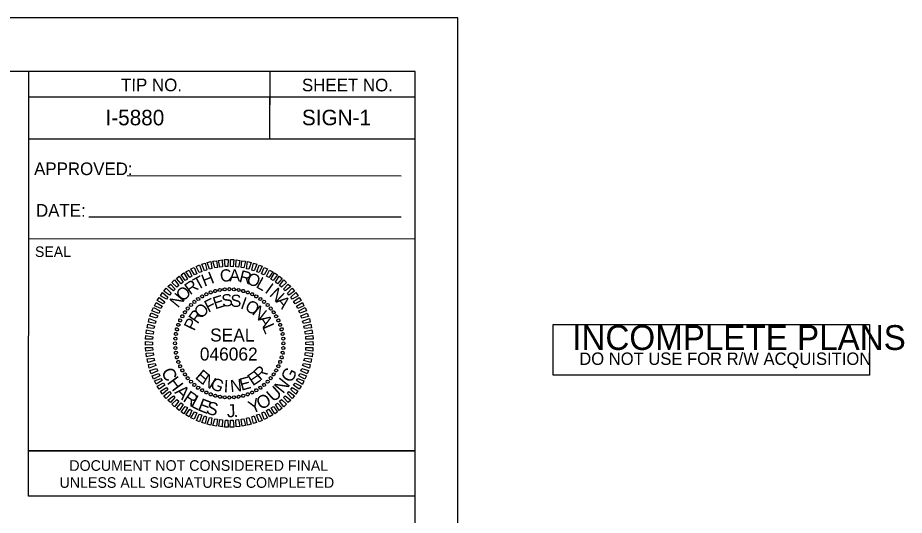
# Model space of a CAD drawing. Extents: x 49201 to 52602, y 49383 to 50479.
# Drawn here: x 52173 to 52602.1, y 50238.5 to 50479.3 of the extents above; entities that cross this region are included whole.
import ezdxf

# ---------------------------------------------------------------- set-up
doc = ezdxf.new("R2010")
doc.units = 0
for name, color, linetype in [('Default', 7, 'Continuous'), ('Old_Level_10', 7, 'Continuous'), ('Old_Level_18', 7, 'Continuous'), ('Old_Level_2', 7, 'Continuous'), ('Old_Level_4', 7, 'Continuous'), ('Old_Level_50', 7, 'Continuous'), ('Sheet Plot Border Outside CELL', 7, 'Continuous'), ('Sheet Sticker Exception Certification CELL', 7, 'Continuous'), ('Sheet Sticker Incomplete CELL', 7, 'Continuous'), ('Sheet Title CELL', 7, 'Continuous')]:
    doc.layers.add(name, color=color, linetype=linetype)

msp = doc.modelspace()

# ---------------------------------------------------------------- linework, layer by layer
at = {"layer": 'Old_Level_10'}
for p, q in [((52295.09, 50420.67), (52295.11, 50453.21)), ((52295.09, 50428.25), (52295.11, 50453.21)), ((52365.34, 50453.17), (52365.34, 50453.17)), ((52178.35, 50441.05), (52295.1, 50440.98)), ((52295.1, 50440.98), (52365.34, 50440.95)), ((52178.34, 50420.73), (52365.33, 50420.63)), ((52226.02, 50402.83), (52358.63, 50402.77)), ((52207.33, 50382.93), (52358.62, 50382.86))]:
    msp.add_line(p, q, dxfattribs=at)
at = {"layer": 'Old_Level_18'}
msp.add_lwpolyline([(52365.34, 50453.17), (50865.34, 50453.17), (50865.34, 49403.17), (52365.34, 49403.17)], close=True, dxfattribs=at)
at = {"layer": 'Old_Level_2'}
for p, q in [((52273.08, 50347.83), (52273.08, 50347.83)), ((52275.38, 50347.93), (52275.38, 50347.93)), ((52277.69, 50347.81), (52277.69, 50347.81)), ((52262.27, 50344.4), (52262.27, 50344.4)), ((52264.29, 50345.48), (52264.29, 50345.48)), ((52266.36, 50346.36), (52266.36, 50346.36)), ((52268.55, 50347.02), (52268.55, 50347.02)), ((52270.84, 50347.48), (52270.84, 50347.48)), ((52279.94, 50347.48), (52279.94, 50347.48)), ((52282.14, 50347.05), (52282.14, 50347.05)), ((52284.35, 50346.36), (52284.35, 50346.36)), ((52286.46, 50345.45), (52286.46, 50345.45)), ((52288.52, 50344.44), (52288.52, 50344.44)), ((52256.8, 50340.23), (52256.8, 50340.23)), ((52258.49, 50341.83), (52258.49, 50341.83)), ((52260.3, 50343.17), (52260.3, 50343.17)), ((52290.42, 50343.17), (52290.42, 50343.17)), ((52292.28, 50341.79), (52292.28, 50341.79)), ((52293.93, 50340.25), (52293.93, 50340.25)), ((52252.6, 50334.82), (52252.6, 50334.82)), ((52253.88, 50336.73), (52253.88, 50336.73)), ((52255.26, 50338.58), (52255.26, 50338.58)), ((52295.52, 50338.55), (52295.52, 50338.55)), ((52296.86, 50336.74), (52296.86, 50336.74)), ((52298.1, 50334.78), (52298.1, 50334.78)), ((52250.69, 50330.66), (52250.69, 50330.66)), ((52251.59, 50332.76), (52251.59, 50332.76)), ((52299.18, 50332.76), (52299.18, 50332.76)), ((52300.05, 50330.68), (52300.05, 50330.68)), ((52249.56, 50326.24), (52249.56, 50326.24)), ((52249.99, 50328.45), (52249.99, 50328.45)), ((52300.72, 50328.5), (52300.72, 50328.5)), ((52301.18, 50326.2), (52301.18, 50326.2)), ((52249.23, 50323.99), (52249.23, 50323.99)), ((52301.53, 50323.96), (52301.53, 50323.96)), ((52249.12, 50321.69), (52249.12, 50321.69)), ((52249.21, 50319.39), (52249.21, 50319.39)), ((52275.37, 50321.67), (52275.37, 50321.67)), ((52301.51, 50319.36), (52301.51, 50319.36)), ((52301.62, 50321.66), (52301.62, 50321.66)), ((52249.56, 50317.14), (52249.56, 50317.14)), ((52250.02, 50314.85), (52250.02, 50314.85)), ((52300.75, 50314.9), (52300.75, 50314.9)), ((52301.18, 50317.1), (52301.18, 50317.1)), ((52250.69, 50312.67), (52250.69, 50312.67)), ((52251.56, 50310.59), (52251.56, 50310.59)), ((52299.15, 50310.58), (52299.15, 50310.58)), ((52300.05, 50312.69), (52300.05, 50312.69)), ((52252.64, 50308.57), (52252.64, 50308.57)), ((52253.88, 50306.6), (52253.88, 50306.6)), ((52255.22, 50304.8), (52255.22, 50304.8)), ((52295.49, 50304.77), (52295.49, 50304.77)), ((52296.87, 50306.62), (52296.87, 50306.62)), ((52298.14, 50308.53), (52298.14, 50308.53)), ((52256.82, 50303.1), (52256.82, 50303.1)), ((52258.46, 50301.56), (52258.46, 50301.56)), ((52292.25, 50301.52), (52292.25, 50301.52)), ((52293.95, 50303.12), (52293.95, 50303.12)), ((52260.32, 50300.18), (52260.32, 50300.18)), ((52262.22, 50298.9), (52262.22, 50298.9)), ((52264.28, 50297.89), (52264.28, 50297.89)), ((52266.39, 50296.99), (52266.39, 50296.99)), ((52268.6, 50296.3), (52268.6, 50296.3)), ((52282.19, 50296.32), (52282.19, 50296.32)), ((52284.38, 50296.99), (52284.38, 50296.99)), ((52286.45, 50297.86), (52286.45, 50297.86)), ((52288.48, 50298.94), (52288.48, 50298.94)), ((52290.44, 50300.18), (52290.44, 50300.18)), ((52270.8, 50295.86), (52270.8, 50295.86)), ((52273.06, 50295.54), (52273.06, 50295.54)), ((52275.36, 50295.42), (52275.36, 50295.42)), ((52277.66, 50295.51), (52277.66, 50295.51)), ((52279.9, 50295.87), (52279.9, 50295.87))]:
    msp.add_line(p, q, dxfattribs=at)
for points in [[(52265.85, 50357.54), (52264.7, 50360.81), (52266.47, 50361.21), (52266.95, 50357.82)], [(52268.35, 50358.16), (52267.46, 50361.49), (52269.18, 50361.68), (52269.61, 50358.34)], [(52270.86, 50358.52), (52270.22, 50361.85), (52272, 50362.09), (52272.11, 50358.69)], [(52273.47, 50358.82), (52273.15, 50362.22), (52274.87, 50362.19), (52274.72, 50358.79)], [(52275.98, 50358.81), (52275.92, 50362.21), (52277.64, 50362.19), (52277.23, 50358.78)], [(52278.59, 50358.7), (52278.74, 50362.11), (52280.48, 50361.82), (52279.85, 50358.52)], [(52281.11, 50358.33), (52281.52, 50361.68), (52283.25, 50361.45), (52282.37, 50358.19)], [(52283.79, 50357.8), (52284.25, 50361.21), (52286.04, 50360.82), (52284.89, 50357.56)], [(52256.3, 50353.5), (52254.32, 50356.29), (52255.92, 50357.16), (52257.28, 50354.15)], [(52258.53, 50354.8), (52256.8, 50357.7), (52258.41, 50358.46), (52259.67, 50355.29)], [(52260.81, 50355.94), (52259.4, 50358.94), (52260.96, 50359.6), (52262.11, 50356.27)], [(52263.36, 50356.82), (52262.1, 50359.93), (52263.71, 50360.43), (52264.45, 50357.2)], [(52286.31, 50357.16), (52287.04, 50360.42), (52288.67, 50359.93), (52287.41, 50356.82)], [(52288.68, 50356.26), (52289.82, 50359.58), (52291.3, 50358.98), (52289.89, 50355.92)], [(52291.05, 50355.31), (52292.3, 50358.42), (52293.93, 50357.72), (52292.21, 50354.76)], [(52293.47, 50354.15), (52294.83, 50357.16), (52296.42, 50356.3), (52294.48, 50353.54)], [(52250, 50348.9), (52247.66, 50351.16), (52248.9, 50352.43), (52250.98, 50349.64)], [(52252.07, 50350.55), (52249.77, 50353.02), (52251.17, 50354.15), (52253.05, 50351.25)], [(52254.02, 50352.16), (52252.04, 50354.79), (52253.39, 50355.81), (52255.16, 50352.8)], [(52295.54, 50352.78), (52297.31, 50355.84), (52298.69, 50354.77), (52296.7, 50352.17)], [(52297.71, 50351.24), (52299.59, 50354.15), (52300.97, 50353.03), (52298.71, 50350.53)], [(52299.72, 50349.66), (52301.82, 50352.41), (52303.1, 50351.18), (52300.73, 50348.89)], [(52246.51, 50345.02), (52243.76, 50347.01), (52244.89, 50348.39), (52247.23, 50345.97)], [(52248.31, 50347.04), (52245.61, 50349.13), (52246.89, 50350.36), (52249.13, 50347.89)], [(52301.64, 50347.86), (52303.84, 50350.36), (52305.12, 50349.13), (52302.44, 50347.04)], [(52303.5, 50346.01), (52305.86, 50348.41), (52306.99, 50347.01), (52304.25, 50344.98)], [(52243.45, 50340.88), (52240.49, 50342.4), (52241.51, 50343.88), (52244.27, 50341.84)], [(52244.98, 50343), (52242.13, 50344.73), (52243.09, 50346.26), (52245.64, 50344.01)], [(52305.1, 50344), (52307.63, 50346.24), (52308.65, 50344.74), (52305.75, 50343.02)], [(52306.5, 50341.88), (52309.24, 50343.92), (52310.26, 50342.36), (52307.25, 50340.85)], [(52242.23, 50338.61), (52239.23, 50339.87), (52239.99, 50341.5), (52242.84, 50339.62)], [(52307.9, 50339.6), (52310.8, 50341.48), (52311.5, 50339.88), (52308.54, 50338.62)], [(52240.22, 50333.87), (52236.97, 50334.76), (52237.62, 50336.39), (52240.78, 50334.98)], [(52241.23, 50336.19), (52237.97, 50337.34), (52238.72, 50338.97), (52241.73, 50337.35)], [(52308.98, 50337.37), (52312.04, 50339), (52312.75, 50337.34), (52309.53, 50336.23)], [(52309.97, 50334.93), (52313.13, 50336.35), (52313.74, 50334.74), (52310.51, 50333.84)], [(52238.85, 50328.83), (52235.6, 50329.19), (52235.93, 50330.97), (52239.25, 50329.93)], [(52239.48, 50331.35), (52236.23, 50331.97), (52236.57, 50333.7), (52239.88, 50332.45)], [(52310.85, 50332.44), (52314.17, 50333.7), (52314.52, 50331.98), (52311.23, 50331.35)], [(52311.52, 50329.94), (52314.8, 50330.99), (52315.14, 50329.22), (52311.85, 50328.85)], [(52238.48, 50326.15), (52235.12, 50326.41), (52235.3, 50328.19), (52238.72, 50327.41)], [(52312.03, 50327.44), (52315.42, 50328.23), (52315.61, 50326.46), (52312.27, 50326.19)], [(52238.25, 50321.03), (52234.86, 50320.81), (52234.83, 50322.59), (52238.23, 50322.28)], [(52238.26, 50323.64), (52234.86, 50323.69), (52234.93, 50325.41), (52238.34, 50324.9)], [(52312.39, 50324.93), (52315.78, 50325.41), (52315.92, 50323.64), (52312.52, 50323.68)], [(52312.49, 50322.32), (52315.89, 50322.54), (52315.92, 50320.76), (52312.51, 50321.07)], [(52238.35, 50318.41), (52234.96, 50317.94), (52234.82, 50319.71), (52238.22, 50319.67)], [(52312.48, 50319.71), (52315.88, 50319.66), (52315.81, 50317.93), (52312.4, 50318.45)], [(52238.71, 50315.91), (52235.32, 50315.12), (52235.13, 50316.89), (52238.48, 50317.16)], [(52239.22, 50313.41), (52235.95, 50312.36), (52235.6, 50314.13), (52238.89, 50314.5)], [(52311.89, 50314.52), (52315.14, 50314.16), (52314.81, 50312.37), (52311.49, 50313.41)], [(52312.27, 50317.19), (52315.62, 50316.94), (52315.44, 50315.16), (52312.03, 50315.93)], [(52239.89, 50310.91), (52236.57, 50309.65), (52236.22, 50311.37), (52239.51, 50312)], [(52240.77, 50308.41), (52237.61, 50307), (52237, 50308.61), (52240.23, 50309.5)], [(52310.52, 50309.47), (52313.78, 50308.59), (52313.12, 50306.96), (52309.96, 50308.37)], [(52311.26, 50312), (52314.51, 50311.37), (52314.18, 50309.64), (52310.86, 50310.89)], [(52241.76, 50305.97), (52238.7, 50304.35), (52237.99, 50306.01), (52241.21, 50307.11)], [(52242.84, 50303.74), (52239.95, 50301.86), (52239.24, 50303.47), (52242.2, 50304.73)], [(52308.51, 50304.73), (52311.51, 50303.48), (52310.76, 50301.84), (52307.9, 50303.73)], [(52309.51, 50307.16), (52312.77, 50306.01), (52312.02, 50304.38), (52309.01, 50306)], [(52244.24, 50301.47), (52241.51, 50299.43), (52240.48, 50300.98), (52243.49, 50302.5)], [(52307.29, 50302.46), (52310.25, 50300.95), (52309.23, 50299.46), (52306.47, 50301.51)], [(52245.64, 50299.35), (52243.11, 50297.11), (52242.09, 50298.61), (52244.99, 50300.33)], [(52247.24, 50297.34), (52244.88, 50294.94), (52243.76, 50296.33), (52246.49, 50298.37)], [(52249.1, 50295.49), (52246.9, 50292.99), (52245.62, 50294.22), (52248.31, 50296.31)], [(52302.43, 50296.31), (52305.14, 50294.21), (52303.85, 50292.99), (52301.61, 50295.46)], [(52304.23, 50298.33), (52306.98, 50296.34), (52305.86, 50294.96), (52303.51, 50297.38)], [(52305.76, 50300.34), (52308.62, 50298.62), (52307.65, 50297.08), (52305.1, 50299.34)], [(52251.02, 50293.69), (52248.92, 50290.93), (52247.65, 50292.17), (52250.01, 50294.46)], [(52253.03, 50292.1), (52251.15, 50289.19), (52249.77, 50290.32), (52252.03, 50292.82)], [(52298.68, 50292.79), (52300.97, 50290.32), (52299.58, 50289.2), (52297.69, 50292.1)], [(52300.74, 50294.45), (52303.08, 50292.19), (52301.85, 50290.92), (52299.76, 50293.7)], [(52255.2, 50290.57), (52253.43, 50287.51), (52252.05, 50288.58), (52254.04, 50291.18)], [(52257.27, 50289.2), (52255.91, 50286.19), (52254.32, 50287.05), (52256.26, 50289.81)], [(52259.69, 50288.04), (52258.44, 50284.93), (52256.81, 50285.63), (52258.53, 50288.59)], [(52292.21, 50288.55), (52293.94, 50285.65), (52292.33, 50284.89), (52291.07, 50288.06)], [(52294.44, 50289.84), (52296.42, 50287.05), (52294.82, 50286.19), (52293.46, 50289.2)], [(52296.72, 50291.19), (52298.7, 50288.56), (52297.36, 50287.54), (52295.58, 50290.54)], [(52262.06, 50287.08), (52260.92, 50283.77), (52259.44, 50284.37), (52260.86, 50287.43)], [(52264.43, 50286.18), (52263.71, 50282.93), (52262.08, 50283.42), (52263.33, 50286.53)], [(52266.95, 50285.55), (52266.49, 50282.14), (52264.71, 50282.53), (52265.85, 50285.79)], [(52269.63, 50285.02), (52269.22, 50281.66), (52267.49, 50281.9), (52268.37, 50285.15)], [(52272.15, 50284.64), (52272, 50281.24), (52270.27, 50281.53), (52270.89, 50284.83)], [(52274.76, 50284.53), (52274.82, 50281.13), (52273.1, 50281.16), (52273.51, 50284.56)], [(52277.27, 50284.52), (52277.6, 50281.13), (52275.87, 50281.15), (52276.02, 50284.55)], [(52279.88, 50284.83), (52280.52, 50281.5), (52278.74, 50281.26), (52278.63, 50284.65)], [(52282.39, 50285.19), (52283.28, 50281.86), (52281.56, 50281.67), (52281.14, 50285.01)], [(52284.89, 50285.81), (52286.04, 50282.53), (52284.27, 50282.14), (52283.79, 50285.53)], [(52287.38, 50286.53), (52288.64, 50283.42), (52287.03, 50282.92), (52286.29, 50286.15)], [(52289.93, 50287.41), (52291.34, 50284.4), (52289.79, 50283.75), (52288.63, 50287.08)]]:
    msp.add_lwpolyline(points, close=True, dxfattribs=at)
for centre, major_axis in [((52268.58, 50347.01), (-0.195, 0.727)), ((52270.82, 50347.5), (-0.131, 0.742)), ((52273.09, 50347.8), (-0.066, 0.75)), ((52275.37, 50347.9), (0, 0.753)), ((52277.66, 50347.8), (0.066, 0.75)), ((52279.93, 50347.5), (0.131, 0.742)), ((52282.16, 50347.01), (0.195, 0.727)), ((52260.33, 50343.16), (-0.432, 0.617)), ((52262.26, 50344.39), (-0.376, 0.652)), ((52264.29, 50345.44), (-0.318, 0.682)), ((52266.4, 50346.32), (-0.258, 0.708)), ((52284.34, 50346.32), (0.258, 0.708)), ((52286.46, 50345.44), (0.318, 0.682)), ((52288.48, 50344.39), (0.376, 0.652)), ((52290.41, 50343.16), (0.432, 0.617)), ((52255.28, 50338.53), (-0.577, 0.484)), ((52256.83, 50340.22), (-0.532, 0.532)), ((52258.51, 50341.77), (-0.484, 0.577)), ((52292.23, 50341.77), (0.484, 0.577)), ((52293.92, 50340.22), (0.532, 0.532)), ((52295.46, 50338.53), (0.577, 0.484)), ((52252.66, 50334.79), (-0.652, 0.376)), ((52253.89, 50336.72), (-0.617, 0.432)), ((52296.86, 50336.72), (0.617, 0.432)), ((52298.08, 50334.79), (0.652, 0.376)), ((52250.72, 50330.64), (-0.708, 0.258)), ((52251.6, 50332.76), (-0.682, 0.318)), ((52299.14, 50332.76), (0.682, 0.318)), ((52300.02, 50330.64), (0.708, 0.258)), ((52249.54, 50326.23), (-0.742, 0.131)), ((52250.04, 50328.46), (-0.727, 0.195)), ((52300.71, 50328.46), (0.727, 0.195)), ((52301.2, 50326.23), (0.742, 0.131)), ((52249.14, 50321.67), (-0.753, 0)), ((52249.24, 50323.96), (-0.75, 0.066)), ((52301.5, 50323.96), (0.75, 0.066)), ((52301.6, 50321.67), (0.753, 0)), ((52249.24, 50319.39), (-0.75, -0.066)), ((52249.54, 50317.12), (-0.742, -0.131)), ((52301.2, 50317.12), (0.742, -0.131)), ((52301.5, 50319.39), (0.75, -0.066)), ((52250.04, 50314.89), (-0.727, -0.195)), ((52250.72, 50312.7), (-0.708, -0.258)), ((52300.02, 50312.7), (0.708, -0.258)), ((52300.71, 50314.89), (0.727, -0.195)), ((52251.6, 50310.59), (-0.682, -0.318)), ((52252.66, 50308.56), (-0.652, -0.376)), ((52298.08, 50308.56), (0.652, -0.376)), ((52299.14, 50310.59), (0.682, -0.318)), ((52253.89, 50306.63), (-0.617, -0.432)), ((52255.28, 50304.81), (-0.577, -0.484)), ((52295.46, 50304.81), (0.577, -0.484)), ((52296.86, 50306.63), (0.617, -0.432)), ((52256.83, 50303.13), (-0.532, -0.532)), ((52258.51, 50301.58), (-0.484, -0.577)), ((52260.33, 50300.19), (-0.432, -0.617)), ((52290.41, 50300.19), (0.432, -0.617)), ((52292.23, 50301.58), (0.484, -0.577)), ((52293.92, 50303.13), (0.532, -0.532)), ((52262.26, 50298.96), (-0.376, -0.652)), ((52264.29, 50297.9), (-0.318, -0.682)), ((52266.4, 50297.03), (-0.258, -0.708)), ((52268.58, 50296.34), (-0.195, -0.727)), ((52270.82, 50295.84), (-0.131, -0.742)), ((52273.09, 50295.55), (-0.066, -0.75)), ((52275.37, 50295.45), (0, -0.753)), ((52277.66, 50295.55), (0.066, -0.75)), ((52279.93, 50295.84), (0.131, -0.742)), ((52282.16, 50296.34), (0.195, -0.727)), ((52284.34, 50297.03), (0.258, -0.708)), ((52286.46, 50297.9), (0.318, -0.682)), ((52288.48, 50298.96), (0.376, -0.652))]:
    msp.add_ellipse(centre, major_axis=major_axis, ratio=0.999708, dxfattribs=at)
at = {"layer": 'Old_Level_50'}
msp.add_line((52386.04, 50479.27), (52386.04, 50479.27), dxfattribs=at)
at = {"layer": 'Sheet Plot Border Outside CELL'}
msp.add_lwpolyline([(52386.04, 50479.27), (50703.13, 50479.27), (50703.13, 49383.36), (52386.04, 49383.36)], close=True, dxfattribs=at)
at = {"layer": 'Sheet Sticker Exception Certification CELL'}
for p, q in [((52178.27, 50247.68), (52178.27, 50269.65)), ((52178.27, 50269.65), (52365.26, 50269.65)), ((52365.26, 50269.63), (52365.26, 50247.67)), ((52365.26, 50247.68), (52178.27, 50247.68))]:
    msp.add_line(p, q, dxfattribs=at)
at = {"layer": 'Sheet Sticker Incomplete CELL'}
msp.add_lwpolyline([(52432.08, 50306.29), (52432.08, 50330.78), (52585.24, 50330.78), (52585.24, 50306.29)], close=True, dxfattribs=at)
at = {"layer": 'Sheet Title CELL'}
for p, q in [((52178.34, 50428.31), (52178.35, 50453.26)), ((52178.32, 50381.13), (52178.34, 50428.31)), ((52178.27, 50269.73), (52178.32, 50381.13)), ((52178.32, 50372.39), (52365.3, 50372.3)), ((52365.26, 50269.65), (52178.27, 50269.73))]:
    msp.add_line(p, q, dxfattribs=at)

# ---------------------------------------------------------------- texts
at = {"layer": 'Default'}
for s, rotation, p in [('C', 297.1998, (52242.25, 50307.94)), ('G', 61.7997, (52305.48, 50302.18)), ('H', 306.6436, (52244.95, 50302.69)), ('N', 51.2288, (52301.4, 50296.98)), ('A', 316.4834, (52248.64, 50297.77)), ('U', 41.4347, (52296.82, 50292.92)), ('R', 325.196, (52252.57, 50294)), ('L', 332.5683, (52256.3, 50291.3)), ('O', 30.0413, (52290.72, 50289.25)), ('E', 338.7524, (52259.69, 50289.42)), ('S', 345.7591, (52263.74, 50287.75)), ('J', 3.0321, (52274.33, 50285.82)), ('Y', 22.2425, (52286.18, 50287.47)), ('.', 8.2139, (52277.57, 50285.87))]:
    msp.add_text(s, height=6.27, rotation=rotation, dxfattribs=at).set_placement(p)
at = {"layer": 'Old_Level_10'}
for s, height, p in [('TIP NO.', 6.11, (52223, 50443.7)), ('SHEET NO.', 6.11, (52310.55, 50443.65)), ('SEAL', 5.094, (52181.34, 50363.48))]:
    msp.add_text(s, height=height, rotation=359.9683, dxfattribs=at).set_placement(p)
at = {"layer": 'Old_Level_2'}
for s, height, rotation, p in [('H', 5.9, 21.6194, (52263.34, 50349.02)), ('C', 5.9, 7.2198, (52271.25, 50351.25)), ('A', 5.9, 0.0203, (52275.37, 50351.64)), ('R', 5.9, 345.6211, (52279.77, 50351.51)), ('R', 5.9, 36.0205, (52256.45, 50344.88)), ('T', 5.9, 28.8197, (52259.97, 50347.24)), ('O', 5.9, 338.4211, (52283.28, 50350.78)), ('L', 5.9, 331.2208, (52287.92, 50348.93)), ('O', 5.9, 43.2217, (52252.9, 50341.57)), ('I', 5.9, 324.0201, (52292.2, 50346.49)), ('N', 5.9, 316.8189, (52294.47, 50344.91)), ('N', 5.9, 50.4235, (52250.55, 50338.5)), ('F', 5.9, 26.967, (52265.23, 50336.45)), ('E', 5.9, 17.611, (52268.55, 50338.08)), ('S', 5.9, 8.2556, (52272.14, 50339.24)), ('S', 5.9, 358.9004, (52275.9, 50339.36)), ('I', 5.9, 340.1896, (52280.41, 50338.71)), ('A', 5.9, 309.6171, (52297.61, 50341.88)), ('O', 5.9, 45.6812, (52261.83, 50333.31)), ('O', 5.9, 330.8335, (52282.51, 50338.01)), ('N', 5.9, 321.4766, (52286.05, 50335.98)), ('R', 5.9, 55.0396, (52260.05, 50330.72)), ('P', 5.9, 64.3989, (52258.43, 50327.34)), ('A', 5.9, 302.7602, (52289.08, 50333.31)), ('L', 5.9, 293.4008, (52291.18, 50329.74)), ('SEAL', 6.273, 360, (52266.1, 50322.56)), ('046062', 6.275, 360, (52261.13, 50313.35)), ('E', 5.9, 319.2769, (52258.51, 50305.01)), ('R', 5.9, 43.4814, (52290.44, 50303.37)), ('N', 5.9, 328.6339, (52261.69, 50302.24)), ('G', 5.9, 337.9902, (52265.71, 50299.96)), ('E', 5.9, 15.4117, (52281.26, 50298.71)), ('E', 5.9, 34.1241, (52286.77, 50300.85)), ('I', 5.9, 356.7012, (52272.59, 50298.09)), ('N', 5.9, 6.0564, (52276.1, 50298))]:
    msp.add_text(s, height=height, rotation=rotation, dxfattribs=at).set_placement(p)
at = {"layer": 'Old_Level_4'}
for s, p in [('APPROVED:', (52180.92, 50403.12)), ('DATE:', (52181.83, 50382.98))]:
    msp.add_text(s, height=6.11, rotation=359.9683, dxfattribs=at).set_placement(p)
at = {"layer": 'Sheet Sticker Exception Certification CELL'}
for s, p in [('DOCUMENT NOT CONSIDERED FINAL', (52197.96, 50259.98)), ('UNLESS ALL SIGNATURES COMPLETED', (52193.22, 50251.75))]:
    msp.add_text(s, height=5.1412, dxfattribs=at).set_placement(p)
at = {"layer": 'Sheet Sticker Incomplete CELL'}
for s, height, p in [('INCOMPLETE PLANS', 12.0025, (52441.4, 50318.48)), ('DO NOT USE FOR R/W ACQUISITION', 6.0012, (52444.79, 50311.24))]:
    msp.add_text(s, height=height, dxfattribs=at).set_placement(p)
at = {"layer": 'Sheet Title CELL'}
for s, p in [('I-5880', (52215.48, 50427.21)), ('SIGN-1', (52310.54, 50427.24))]:
    msp.add_text(s, height=7.5, rotation=359.9683, dxfattribs=at).set_placement(p)

doc.saveas('drawing.dxf')
